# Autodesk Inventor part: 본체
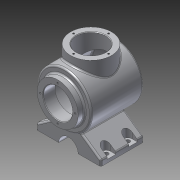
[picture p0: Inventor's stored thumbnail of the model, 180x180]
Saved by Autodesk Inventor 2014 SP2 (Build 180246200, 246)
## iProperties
Created: 2017-04
Part Number: 본체
Material: 알루미늄 6061
Document SubType Name: Modeling
Designer: 거성
Density: 2.71 g/cm^3
Appearance: 알루미늄 - 평지
Author: 거성
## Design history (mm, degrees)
sketch "스케치4"
  geometry: L1 (0, -54)-(0, 54); L2 (0, 54)-(50, 54); L3 (50, 54)-(50, -42.336); L4 (0, 44)-(40, 44); L5 (40, 44)-(40, -35.916); L6 (0, -54)-(0, -44); L7 (0, 44)-(0, 54); A1 r 113 centre (0, 59) between (0, -54) and (50, -42.336); A2 r 103 centre (0, 59) between (0, -44) and (40, -35.916); 2 further points
  constraints: 14 end point, 4 point on circle, 2 centre point, 2 collinear, 2 parallel, 2 perpendicular, 1 coincident, 1 midpoint, 1 vertical
  dimensions: "d31" = 108 distance of L1.start L1.end; "d32" = 226 diameter of A1; "d33" = 100 diameter of L3 L1; "d34" = 50 distance from line of L3 A1.centre; "d35" = 10 radial gap between concentric circles of A1 A2; "d36" = 10 distance between parallel lines of L3 L5; "d37" = 10 distance between parallel lines of L2 L4
revolve "회전2" sketch "스케치4" stored, may be unused: angle "d38" = 90 deg
sketch "스케치5"
  geometry: C1 r 50 at (0, 0) reference; C2 r 38 at (0, 0)
  constraints: 1 centre point, 1 coincident
  dimensions: "d39" = 76 diameter of C2
extrude "돌출3" join sketch "스케치5" distance "d40" = 12; taper "d41" = 0 deg
sketch "스케치6"
  geometry: C1 r 38 at (0, 0) reference; C2 r 27 at (0, 0)
  constraints: 1 centre point, 1 coincident
  dimensions: "d42" = 54 diameter of C2
extrude "돌출4" cut sketch "스케치6" distance "d43" = 22; taper "d44" = 0 deg
node "작업 평면4"
sketch "스케치7"
  geometry: L1 (21.584, -45.101)-(60, -72); L2 (60, -72)-(60, -82); L3 (60, -82)-(-60, -82); L4 (-60, -82)-(-60, -72); L5 (-60, -72)-(-21.584, -45.101); A1 r 50 centre (0, 0) between (21.584, -45.101) and (-21.584, -45.101) reference; 2 further points
  constraints: 10 end point, 2 perpendicular, 2 point on circle, 1 midpoint, 1 parallel, 1 vertical, 1 vertical alignment
  dimensions: "d46" = 120 distance of L2.end L3.end; "d47" = 10 distance of L1.end L2.end; "d48" = 55 deg angle of L1 L2; "d49" = 55 deg angle of L4 L5; "d50" = 82 distance from line of L3 point (0, 0)
extrude "돌출5" join sketch "스케치7" distance "d51" = 80; taper "d52" = 0 deg
sketch "스케치8"
  geometry: L1 (-60, -82)-(60, -82) reference; C1 r 18 at (0, -82); 1 further point
  constraints: 1 centre point, 1 midpoint
  dimensions: "d53" = 36 diameter of C1
extrude "돌출6" cut sketch "스케치8" distance "d54" = 80; taper "d55" = 0 deg
node "작업 평면5"
sketch "스케치12" dims "d74" = 65
  geometry: C1 r 38 at (0, 0) reference; 2 further points
  constraints: 2 vertical alignment, 1 coincident, 2 other
hole "구멍2" sketch "스케치12" at (0, 32.5) diameter "d75" = 3.242; stored, may be unused: countersink angle "d79" = 82 deg, drill point angle "d81" = 118 deg; dims "d76" = 8, "d77" = 3.023, "d78" = 2, "d80" = 10
node "작업 평면6"
sketch "스케치13"
  geometry: L1 (-10, 68)-(0, 68); L2 (-10, 52)-(0, 52); L3 (-10, 28)-(0, 28); L4 (-10, 12)-(0, 12); L5 (0, 80)-(0, 0) reference; L6 (0, 80)-(-38.416, 80) reference; A1 r 8 centre (-10, 60) between (-10, 68) and (-10, 52); A2 r 8 centre (-10, 20) between (-10, 28) and (-10, 12); 1 further point
  constraints: 8 end point, 4 point on circle, 4 point on line, 4 tangent, 3 parallel, 2 centre point, 1 horizontal
  dimensions: "d86" = 16 diameter of A1; "d87" = 16 diameter of A2; "d88" = 10 distance from line of L5 A1.centre; "d89" = 20 distance from line of L6 A1.centre; "d90" = 40 distance of A2.centre A1.centre; "d91" = 10 distance of L4.start L4.end
extrude "돌출9" cut sketch "스케치13" distance "d92" = 40; taper "d93" = 0 deg
sketch "스케치14"
  geometry: C1 r 4 at (-10, -20); C2 r 4 at (-10, -60); A1 r 8 centre (-10, -20) between (-10, -12) and (-10, -28) reference; A2 r 8 centre (-10, -60) between (-10, -52) and (-10, -68) reference; 1 further point
  constraints: 2 centre point, 2 coincident
  dimensions: "d94" = 8 diameter of C1; "d95" = 8 diameter of C2
extrude "돌출10" cut sketch "스케치14" distance "d96" = 40; taper "d97" = 0 deg
fillet "모깎기2" dims "d99" = 3
fillet "모깎기3" dims "d100" = 3
fillet "모깎기4" dims "d101" = 3
fillet "모깎기5" dims "d102" = 3
node "작업 평면13"
sketch "스케치21"
  geometry: L1 (-50, 54)-(50, 54) reference; C1 r 38 at (0, 4); 1 further point
  constraints: 1 centre point, 1 vertical alignment
  dimensions: "d112" = 76 diameter of C1; "d113" = 50 distance from line of C1.centre L1
extrude "돌출11" join sketch "스케치21" stored distance "d114" = 40; taper "d115" = 0 deg
sketch "스케치22"
  geometry: C1 r 38 at (0, 0) reference; C2 r 27 at (0, 0); 1 further point
  constraints: 1 centre point, 1 coincident
  dimensions: "d116" = 54 diameter of C2
extrude "돌출12" cut sketch "스케치22" stored distance "d117" = 40; taper "d118" = 0 deg
sketch "스케치23" dims "d119" = 65
  geometry: C1 r 38 at (0, 0) reference; 3 further points
  constraints: 2 vertical alignment, 1 coincident, 2 other
hole "구멍3" sketch "스케치23" at (0, 32.5) diameter "d120" = 3.242; stored, may be unused: countersink angle "d124" = 82 deg, drill point angle "d126" = 118 deg; dims "d121" = 8, "d122" = 3.023, "d123" = 2, "d125" = 10
chamfer "모따기2" distance "d130" = 1; stored, may be unused: second distance "d131" = 2, angle "d132" = 45 deg
fillet "모깎기6" dims "d133" = 3
node "솔리드2"
pattern_circular "원형 패턴2" dims angle "d83" = 360 deg
mirror "대칭1"
pattern_circular "원형 패턴3" dims angle "d128" = 360 deg
other parameters: "d45" = -8, "d56" = 65, "d85" = -6, "d111" = 65
